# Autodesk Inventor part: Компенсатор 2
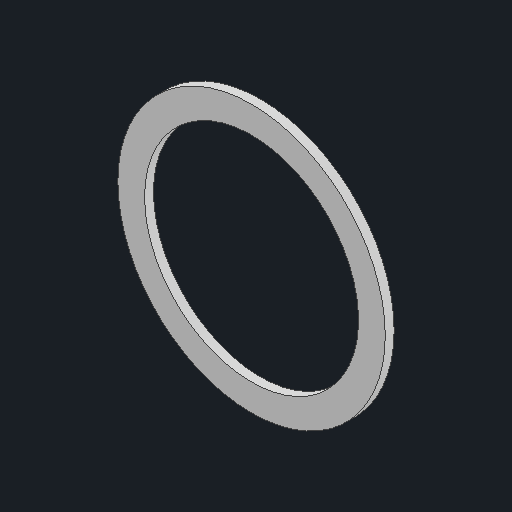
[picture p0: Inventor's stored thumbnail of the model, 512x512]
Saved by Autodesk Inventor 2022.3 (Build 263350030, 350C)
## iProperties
Created: 2020-09
Part Number: Компенсатор 2
Material: Типовые
Document SubType Name: Modeling
Designer: Карташов
Density: 1 g/cm^3
Appearance: По умолчанию
Title: D:\мои документы\Ирина\_WorldSkills\2020_09 ФНЧ\Module A\Участникам\GIVEN\Компенсатор 2.stp
Author: Дом
Sending System: Autodesk Inventor 2021
Preprocessor: ST-DEVELOPER v18.1
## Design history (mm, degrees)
feature "Твердое тело2"
node "Твердое тело1"
